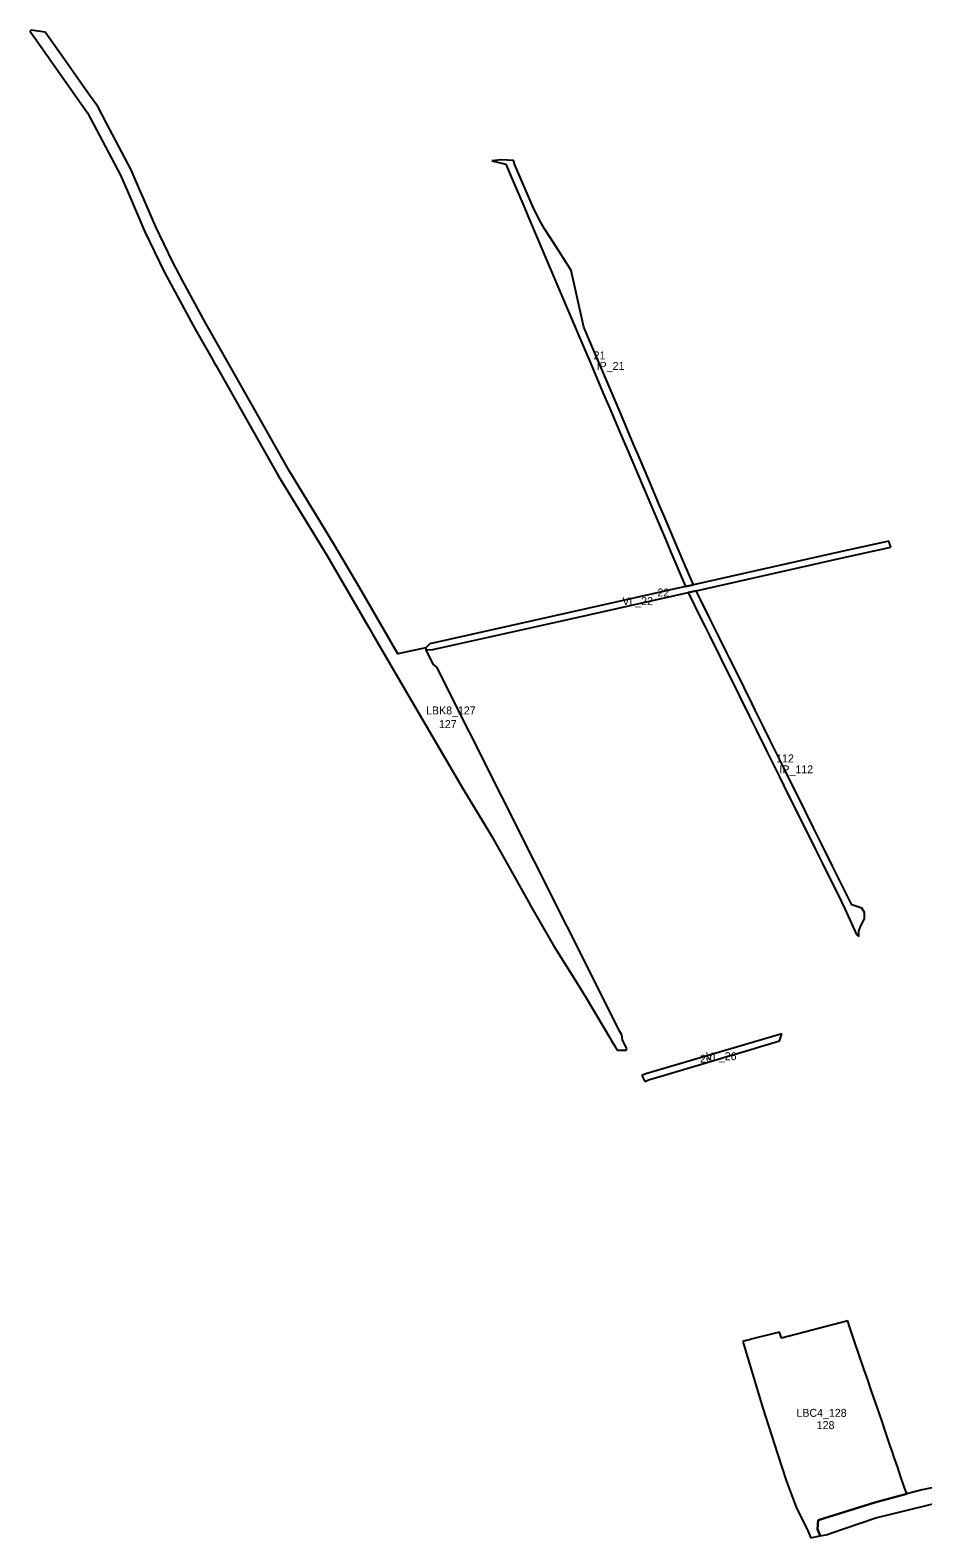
# Model space of a CAD drawing. Extents: x -521939 to -518034, y -1194984 to -1189555.
# Drawn here: x -521939 to -520815, y -1192801 to -1190901 of the extents above; entities that cross this region are included whole.
import ezdxf

# ---------------------------------------------------------------- set-up
doc = ezdxf.new("R2010")
doc.units = 0
for name, color, linetype in [('96120023', 7, 'Continuous'), ('96140023', 7, 'Continuous'), ('ID VPO', 7, 'Continuous'), ('ID VPS', 7, 'Continuous')]:
    doc.layers.add(name, color=color, linetype=linetype)

msp = doc.modelspace()

# ---------------------------------------------------------------- linework, layer by layer
at = {"layer": '96120023'}
for points in [[(-521330.04, -1191065.83), (-521337.72, -1191065.02), (-521345.44, -1191064.87), (-521357.75, -1191066.04)], [(-521357.75, -1191066.04), (-521339.87, -1191070.1)], [(-521328.5, -1191071.27), (-521330.04, -1191065.83)], [(-521339.87, -1191070.1), (-521333.03, -1191086.18)], [(-521306.22, -1191122.56), (-521328.5, -1191071.27)], [(-521333.03, -1191086.18), (-521316.14, -1191125.96)], [(-521298.06, -1191140.03), (-521306.22, -1191122.56)], [(-521316.14, -1191125.96), (-521309.96, -1191140.46)], [(-521309.96, -1191140.46), (-521300.29, -1191163.2)], [(-521291.03, -1191151.73), (-521298.06, -1191140.03)], [(-521283.87, -1191162.75), (-521291.03, -1191151.73)], [(-521300.29, -1191163.2), (-521277.99, -1191215.69)], [(-521264.02, -1191194.06), (-521283.87, -1191162.75)], [(-521253.66, -1191221.09), (-521257.44, -1191204.41), (-521264.02, -1191194.06)], [(-521277.99, -1191215.69), (-521268.33, -1191238.36)], [(-521247.03, -1191251.47), (-521253.66, -1191221.09)], [(-521268.33, -1191238.36), (-521262.5, -1191252.21)], [(-521262.5, -1191252.21), (-521240.42, -1191304.4)], [(-521234.63, -1191292.32), (-521241.56, -1191275.78), (-521247.03, -1191251.47)], [(-521214.55, -1191339.42), (-521234.63, -1191292.32)], [(-521240.42, -1191304.4), (-521233.83, -1191319.62)], [(-521233.83, -1191319.62), (-521222.21, -1191346.98)], [(-521222.21, -1191346.98), (-521215.47, -1191362.92)], [(-521193.95, -1191387.89), (-521214.55, -1191339.42)], [(-521215.47, -1191362.92), (-521209, -1191378.24)], [(-521209, -1191378.24), (-521195.36, -1191410.11)], [(-521179.31, -1191422.24), (-521193.95, -1191387.89)], [(-521195.36, -1191410.11), (-521191.65, -1191418.82)], [(-521191.65, -1191418.82), (-521187.14, -1191429.23)], [(-521170.39, -1191443.27), (-521179.31, -1191422.24)], [(-521187.14, -1191429.23), (-521159.78, -1191493.6)], [(-521167.05, -1191451.05), (-521170.39, -1191443.27)], [(-521158.65, -1191470.84), (-521167.05, -1191451.05)], [(-521146.18, -1191500.28), (-521158.65, -1191470.84)], [(-521159.78, -1191493.6), (-521152.49, -1191510.64)], [(-521141.21, -1191511.9), (-521146.18, -1191500.28)], [(-521152.49, -1191510.64), (-521146.31, -1191525.29)], [(-521128.68, -1191541.41), (-521141.21, -1191511.9)], [(-521146.31, -1191525.29), (-521138.81, -1191542.98)], [(-521138.81, -1191542.98), (-521131.85, -1191559.38)], [(-521131.85, -1191559.38), (-521113.53, -1191602.49)], [(-521115.6, -1191572.16), (-521128.68, -1191541.41)], [(-520857.48, -1191545.13), (-520926.4, -1191560.57), (-521103.61, -1191600.27)], [(-521100.31, -1191607.72), (-520917.76, -1191566.84), (-520854.89, -1191552.76)], [(-520854.89, -1191552.76), (-520857.48, -1191545.13)], [(-521103.61, -1191600.27), (-521115.6, -1191572.16)], [(-521113.53, -1191602.49), (-521257.76, -1191634.79), (-521435.48, -1191674.59)], [(-521258.02, -1191643.05), (-521110.35, -1191609.97)], [(-521113.53, -1191602.49), (-521103.61, -1191600.27)], [(-521103.61, -1191600.27), (-521113.53, -1191602.49)], [(-521110.35, -1191609.97), (-521100.31, -1191607.72)], [(-521100.31, -1191607.72), (-521110.35, -1191609.97)], [(-521110.35, -1191609.97), (-521094.53, -1191641.74)], [(-521094.71, -1191618.99), (-521100.31, -1191607.72)], [(-521083.44, -1191641.83), (-521094.71, -1191618.99)], [(-521431.76, -1191681.97), (-521258.02, -1191643.05)], [(-521094.53, -1191641.74), (-521088.54, -1191653.97)], [(-521088.54, -1191653.97), (-521082.93, -1191665.23)], [(-521075.75, -1191657.25), (-521083.44, -1191641.83)], [(-521082.93, -1191665.23), (-521069.59, -1191692.15)], [(-521072.03, -1191664.78), (-521075.75, -1191657.25)], [(-521061.5, -1191686.09), (-521072.03, -1191664.78)], [(-521435.48, -1191674.59), (-521440.71, -1191679.65)], [(-521440.71, -1191679.65), (-521440.4, -1191682.13)], [(-521440.4, -1191682.13), (-521431.76, -1191681.97)], [(-521069.59, -1191692.15), (-521045.95, -1191739.73)], [(-521058, -1191692.92), (-521061.5, -1191686.09)], [(-521052.87, -1191703.37), (-521058, -1191692.92)], [(-521039.79, -1191729.8), (-521052.87, -1191703.37)], [(-521029.7, -1191750.25), (-521039.79, -1191729.8)], [(-521045.95, -1191739.73), (-521033.33, -1191765.25)], [(-521033.33, -1191765.25), (-521024.18, -1191783.72), (-521011.95, -1191808.58)], [(-521025.6, -1191758.4), (-521029.7, -1191750.25)], [(-521015.3, -1191779.24), (-521025.6, -1191758.4)], [(-521006.81, -1191796.39), (-521015.3, -1191779.24)], [(-520989.64, -1191831.01), (-521006.81, -1191796.39)], [(-521011.95, -1191808.58), (-520995.26, -1191842.12)], [(-520995.26, -1191842.12), (-520983.63, -1191865.68)], [(-520981.65, -1191847.19), (-520989.64, -1191831.01)], [(-520965.82, -1191878.99), (-520981.65, -1191847.19)], [(-520983.63, -1191865.68), (-520959.52, -1191914.15)], [(-520952.13, -1191906.66), (-520961.83, -1191887.02), (-520965.82, -1191878.99)], [(-520959.52, -1191914.15), (-520949.74, -1191933.88)], [(-520941.86, -1191927.51), (-520952.13, -1191906.66)], [(-520949.74, -1191933.88), (-520941.03, -1191951.61), (-520931.19, -1191971.43)], [(-520928.16, -1191955.01), (-520941.86, -1191927.51)], [(-520919.89, -1191971.66), (-520928.16, -1191955.01)], [(-520931.19, -1191971.43), (-520921.84, -1191990.28)], [(-520912.07, -1191987.5), (-520919.89, -1191971.66)], [(-520921.84, -1191990.28), (-520912.71, -1192008.61)], [(-520897.64, -1192005.71), (-520904.09, -1192003.54), (-520912.07, -1191987.5)], [(-520912.71, -1192008.61), (-520898.22, -1192040.98)], [(-520895.08, -1192040.13), (-520895.06, -1192036.66), (-520893.18, -1192030.83), (-520888.16, -1192021.2), (-520888.12, -1192013.43), (-520891.41, -1192007.81), (-520897.64, -1192005.71)], [(-520898.22, -1192040.98), (-520895.11, -1192043.42)], [(-520895.11, -1192043.42), (-520895.08, -1192040.13)], [(-520992.3, -1192166.01), (-521163.51, -1192216.7)], [(-520994.96, -1192175.05), (-520992.3, -1192166.01)], [(-521038.14, -1192187.92), (-521020.52, -1192182.75)], [(-521020.52, -1192182.75), (-521008.84, -1192179.25)], [(-521008.84, -1192179.25), (-520994.96, -1192175.05)], [(-521111.98, -1192209.79), (-521097.8, -1192205.47)], [(-521097.8, -1192205.47), (-521072.45, -1192198.08)], [(-521072.45, -1192198.08), (-521057.45, -1192193.65)], [(-521057.45, -1192193.65), (-521038.14, -1192187.92)], [(-521163.51, -1192216.7), (-521168.5, -1192218.83)], [(-521168.5, -1192218.83), (-521164.96, -1192226.12)], [(-521164.96, -1192226.12), (-521160.1, -1192224.03)], [(-521160.1, -1192224.03), (-521140.15, -1192218.12)], [(-521140.15, -1192218.12), (-521111.98, -1192209.79)]]:
    msp.add_lwpolyline(points, dxfattribs=at)
at = {"layer": '96140023'}
for points in [[(-521937.86, -1190901.38), (-521939.16, -1190903.04), (-521935.96, -1190907.57)], [(-521920.24, -1190903.83), (-521937.86, -1190901.38)], [(-521935.96, -1190907.57), (-521933.74, -1190910.72)], [(-521933.74, -1190910.72), (-521866.8, -1191005.56), (-521825.27, -1191083.96)], [(-521895.95, -1190938.24), (-521920.24, -1190903.83)], [(-521864.2, -1190983.23), (-521895.95, -1190938.24)], [(-521842.92, -1191018.58), (-521853.99, -1190997.69), (-521864.2, -1190983.23)], [(-521819.76, -1191062.36), (-521842.92, -1191018.58)], [(-521811.73, -1191077.48), (-521819.76, -1191062.36)], [(-521825.27, -1191083.96), (-521815.35, -1191107.04)], [(-521800.42, -1191103.83), (-521811.73, -1191077.48)], [(-521796.68, -1191112.46), (-521800.42, -1191103.83)], [(-521815.35, -1191107.04), (-521794.55, -1191155.45), (-521770.21, -1191205.78), (-521731.15, -1191278.24), (-521709.89, -1191315.39)], [(-521785.08, -1191139.7), (-521796.68, -1191112.46)], [(-521759.83, -1191192.86), (-521780.9, -1191149.22), (-521785.08, -1191139.7)], [(-521747.24, -1191216.9), (-521759.83, -1191192.86)], [(-521699.07, -1191304.11), (-521718.04, -1191270.95), (-521747.24, -1191216.9)], [(-521655.79, -1191380.73), (-521699.07, -1191304.11)], [(-521709.89, -1191315.39), (-521706.74, -1191320.96)], [(-521706.74, -1191320.96), (-521704.75, -1191324.48)], [(-521704.75, -1191324.48), (-521626.26, -1191463.39)], [(-521630.25, -1191425.87), (-521655.79, -1191380.73)], [(-521555.8, -1191550.34), (-521613.32, -1191455.79), (-521630.25, -1191425.87)], [(-521626.26, -1191463.39), (-521565.51, -1191562.94)], [(-521524.4, -1191603.79), (-521555.8, -1191550.34)], [(-521565.51, -1191562.94), (-521512.5, -1191654.17)], [(-521440.71, -1191679.65), (-521475.77, -1191687.37), (-521524.4, -1191603.79)], [(-521512.5, -1191654.17), (-521507.47, -1191662.82)], [(-521507.47, -1191662.82), (-521475.16, -1191718.42)], [(-521440.4, -1191682.13), (-521440.71, -1191679.65)], [(-521263.12, -1192029.99), (-521345.06, -1191867.15), (-521427, -1191704.31), (-521431.33, -1191700.15), (-521440.4, -1191682.13)], [(-521475.16, -1191718.42), (-521440.41, -1191778.22), (-521394.07, -1191856.97)], [(-521394.07, -1191856.97), (-521358.15, -1191916.77), (-521340.67, -1191947.49), (-521311.39, -1192000)], [(-521311.39, -1192000), (-521308.38, -1192005.41)], [(-521308.38, -1192005.41), (-521279.68, -1192054.79), (-521250, -1192102.48)], [(-521193.86, -1192167.63), (-521196.15, -1192163.08), (-521263.12, -1192029.99)], [(-521250, -1192102.48), (-521238.5, -1192120.96), (-521209.18, -1192170.31)], [(-521193.11, -1192173.56), (-521193.86, -1192167.63)], [(-521209.18, -1192170.31), (-521207.02, -1192173.96)], [(-521207.02, -1192173.96), (-521201.6, -1192183.07)], [(-521201.6, -1192183.07), (-521199.33, -1192186.9)], [(-521199.33, -1192186.9), (-521188.6, -1192186.94), (-521187.37, -1192184.96)], [(-521187.37, -1192184.96), (-521193.11, -1192173.56)], [(-520908.99, -1192527.86), (-520992.77, -1192549.69)], [(-520903.57, -1192544.89), (-520907.44, -1192533.58), (-520908.21, -1192530.72), (-520908.99, -1192527.86)], [(-520995.13, -1192542.04), (-521030.87, -1192551.11)], [(-520992.77, -1192549.69), (-520995.13, -1192542.04)], [(-520899.67, -1192556.33), (-520903.57, -1192544.89)], [(-521037.14, -1192552.7), (-521041.32, -1192553.76)], [(-521041.32, -1192553.76), (-521016.55, -1192636.53)], [(-521033.12, -1192551.66), (-521036.09, -1192552.43), (-521037.14, -1192552.7)], [(-521030.87, -1192551.11), (-521033.12, -1192551.66)], [(-520895.43, -1192568.72), (-520899.67, -1192556.33)], [(-520888.34, -1192589.46), (-520895.43, -1192568.72)], [(-520884.03, -1192602.07), (-520888.34, -1192589.46)], [(-520879.59, -1192615.06), (-520884.03, -1192602.07)], [(-520871.37, -1192639.12), (-520879.59, -1192615.06)], [(-521016.55, -1192636.53), (-520997.18, -1192696.65)], [(-520869.28, -1192645.23), (-520871.37, -1192639.12)], [(-520866, -1192654.84), (-520869.28, -1192645.23)], [(-520861.2, -1192668.88), (-520866, -1192654.84)], [(-520855.19, -1192686.47), (-520861.2, -1192668.88)], [(-520997.18, -1192696.65), (-520986.7, -1192729.16), (-520974.15, -1192762.68), (-520959.24, -1192792.44)], [(-520853.74, -1192690.71), (-520855.19, -1192686.47)], [(-520850.47, -1192700.26), (-520853.74, -1192690.71)], [(-520596.04, -1192695.13), (-520758.3, -1192728.9), (-520815.45, -1192740.8), (-520834.88, -1192746.05)], [(-520846.21, -1192712.75), (-520850.47, -1192700.26)], [(-520842.13, -1192724.66), (-520846.21, -1192712.75)], [(-520840.49, -1192729.47), (-520842.13, -1192724.66)], [(-520837.96, -1192736.86), (-520840.49, -1192729.47)], [(-520834.88, -1192746.05), (-520835.3, -1192744.66), (-520837.96, -1192736.86)], [(-520874.84, -1192756.86), (-520946.38, -1192779.22)], [(-520946.38, -1192779.22), (-520874.84, -1192756.86)], [(-520930.47, -1192795.56), (-520873.66, -1192776.25), (-520770.76, -1192750.7)], [(-520834.88, -1192746.05), (-520874.84, -1192756.86)], [(-520874.84, -1192756.86), (-520834.88, -1192746.05)], [(-520959.24, -1192792.44), (-520955.72, -1192801.31)], [(-520946.38, -1192779.22), (-520947.19, -1192790.27)], [(-520947.19, -1192790.27), (-520946.38, -1192779.22)], [(-520947.19, -1192790.27), (-520944.08, -1192798.91)], [(-520944.08, -1192798.91), (-520947.19, -1192790.27)], [(-520955.72, -1192801.31), (-520948.03, -1192799.73)], [(-520948.03, -1192799.73), (-520944.08, -1192798.91)], [(-520944.08, -1192798.91), (-520934.56, -1192796.95), (-520930.47, -1192795.56)]]:
    msp.add_lwpolyline(points, dxfattribs=at)

# ---------------------------------------------------------------- texts
at = {"layer": '96120023'}
for s, rotation, p in [('IP_21', 0, (-521225.45, -1191329.46)), ('VL_22', 0, (-521193.17, -1191625.95)), ('IP_112', 0, (-520995.19, -1191837.92)), ('VL_26', 360, (-521087.9, -1192199.36))]:
    msp.add_text(s, height=10, rotation=rotation, dxfattribs=at).set_placement(p)
at = {"layer": '96140023'}
for s, rotation, p in [('LBK8_127', 0, (-521440.4, -1191763.67)), ('LBC4_128', 360, (-520973.75, -1192648.79))]:
    msp.add_text(s, height=10, rotation=rotation, dxfattribs=at).set_placement(p)
at = {"layer": 'ID VPO'}
for s, p in [('127', (-521424.17, -1191780.86)), ('128', (-520948.2, -1192664.3))]:
    msp.add_text(s, height=10, rotation=0, dxfattribs=at).set_placement(p)
at = {"layer": 'ID VPS'}
for s, rotation, p in [('21', 0, (-521229.32, -1191316.29)), ('22', 360, (-521148.9, -1191615.04)), ('112', 0, (-520999.36, -1191824.08)), ('26', 360, (-521095.31, -1192202.47))]:
    msp.add_text(s, height=10, rotation=rotation, dxfattribs=at).set_placement(p)

doc.saveas('drawing.dxf')
